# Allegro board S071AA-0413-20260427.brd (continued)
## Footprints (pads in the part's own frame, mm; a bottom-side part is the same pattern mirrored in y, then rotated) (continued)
LOGO_FY_FARADAY
  rect 4.678x4.678 smd rot 135: (-48.296,3.668) (-44.629,7.334) (-44.629,0.001) (-40.962,11.001) (-40.962,-3.666) (-37.296,0.001) (-37.296,-7.333)
  round 0.051 smd: 1(0.831,1.487)
LOGO_KT_KSMT
  round 0.051 smd: 1(-0.711,-0.711)
M3_NPTH169
  round 0.508 hole 4.293 unplated: (0,0)
OSC_3P2X2P5_4P_AKER
  rect 1.397x1.016 smd: 1(-1.1,-0.8) 2(1.1,-0.8) 3(1.1,0.8) 4(-1.1,0.8)
PCB_CODE
  round 0.051 smd: 1(0,0)
PG_VG93K_F_G1D101
  round 1.778 hole 0.711: 01(-20.32,-1.27) 02(-17.78,1.27) 03(-15.24,-1.27) 04(-12.7,1.27) 05(-10.16,-1.27) 06(-7.62,1.27) 07(-5.08,-1.27) 08(-2.54,1.27) 09(0,-1.27) 10(2.54,1.27) 11(5.08,-1.27) 12(7.62,1.27) 13(10.16,-1.27) 14(12.7,1.27) 15(15.24,-1.27) 16(17.78,1.27) 17(20.32,-1.27)
  rect 1.778x1.778 hole 0.711: A1(-20.32,-3.81) A2(-17.78,-1.27) A3(-15.24,-3.81) A4(-12.7,-1.27) A5(-10.16,-3.81) A6(-7.62,-1.27) A7(-5.08,-3.81) A8(-2.54,-1.27) A9(0,-3.81) A10(2.54,-1.27) A11(5.08,-3.81) A12(7.62,-1.27) A13(10.16,-3.81) A14(12.7,-1.27) A15(15.24,-3.81) A16(17.78,-1.27) A17(20.32,-3.81) B1(-20.32,1.27) B2(-17.78,3.81) B3(-15.24,1.27) B4(-12.7,3.81) B5(-10.16,1.27) B6(-7.62,3.81) B7(-5.08,1.27) B8(-2.54,3.81) B9(0,1.27) B10(2.54,3.81) B11(5.08,1.27) B12(7.62,3.81) B13(10.16,1.27) B14(12.7,3.81) B15(15.24,1.27) B16(17.78,3.81) B17(20.32,1.27)
PG_VG93K_F_G1D102
  round 1.778 hole 0.711: 01(-20.32,-1.27) 02(-17.78,1.27) 03(-15.24,-1.27) 04(-12.7,1.27) 05(-10.16,-1.27) 06(-7.62,1.27) 07(-5.08,-1.27) 08(-2.54,1.27) 09(0,-1.27) 10(2.54,1.27) 11(5.08,-1.27) 12(7.62,1.27) 13(10.16,-1.27) 14(12.7,1.27) 15(15.24,-1.27) 16(17.78,1.27) 17(20.32,-1.27)
  rect 1.778x1.778 hole 0.711: A1(-20.32,-3.81) A2(-17.78,-1.27) A3(-15.24,-3.81) A4(-12.7,-1.27) A5(-10.16,-3.81) A6(-7.62,-1.27) A7(-5.08,-3.81) A8(-2.54,-1.27) A9(0,-3.81) A10(2.54,-1.27) A11(5.08,-3.81) A12(7.62,-1.27) A13(10.16,-3.81) A14(12.7,-1.27) A15(15.24,-3.81) A16(17.78,-1.27) A17(20.32,-3.81) B1(-20.32,1.27) B2(-17.78,3.81) B3(-15.24,1.27) B4(-12.7,3.81) B5(-10.16,1.27) B6(-7.62,3.81) B7(-5.08,1.27) B8(-2.54,3.81) B9(0,1.27) B10(2.54,3.81) B11(5.08,1.27) B12(7.62,3.81) B13(10.16,1.27) B14(12.7,3.81) B15(15.24,1.27) B16(17.78,3.81) B17(20.32,1.27)
PG_VG93K_F_G1D103
  round 1.778 hole 0.711: 01(-20.32,-1.27) 02(-17.78,1.27) 03(-15.24,-1.27) 04(-12.7,1.27) 05(-10.16,-1.27) 06(-7.62,1.27) 07(-5.08,-1.27) 08(-2.54,1.27) 09(0,-1.27) 10(2.54,1.27) 11(5.08,-1.27) 12(7.62,1.27) 13(10.16,-1.27) 14(12.7,1.27) 15(15.24,-1.27) 16(17.78,1.27) 17(20.32,-1.27)
  rect 1.778x1.778 hole 0.711: A1(-20.32,-3.81) A2(-17.78,-1.27) A3(-15.24,-3.81) A4(-12.7,-1.27) A5(-10.16,-3.81) A6(-7.62,-1.27) A7(-5.08,-3.81) A8(-2.54,-1.27) A9(0,-3.81) A10(2.54,-1.27) A11(5.08,-3.81) A12(7.62,-1.27) A13(10.16,-3.81) A14(12.7,-1.27) A15(15.24,-3.81) A16(17.78,-1.27) A17(20.32,-3.81) B1(-20.32,1.27) B2(-17.78,3.81) B3(-15.24,1.27) B4(-12.7,3.81) B5(-10.16,1.27) B6(-7.62,3.81) B7(-5.08,1.27) B8(-2.54,3.81) B9(0,1.27) B10(2.54,3.81) B11(5.08,1.27) B12(7.62,3.81) B13(10.16,1.27) B14(12.7,3.81) B15(15.24,1.27) B16(17.78,3.81) B17(20.32,1.27)
PG_VG93K_F_G1D104
  round 1.778 hole 0.711: 01(-20.32,-1.27) 02(-17.78,1.27) 03(-15.24,-1.27) 04(-12.7,1.27) 05(-10.16,-1.27) 06(-7.62,1.27) 07(-5.08,-1.27) 08(-2.54,1.27) 09(0,-1.27) 10(2.54,1.27) 11(5.08,-1.27) 12(7.62,1.27) 13(10.16,-1.27) 14(12.7,1.27) 15(15.24,-1.27) 16(17.78,1.27) 17(20.32,-1.27)
  rect 1.778x1.778 hole 0.711: A1(-20.32,-3.81) A2(-17.78,-1.27) A3(-15.24,-3.81) A4(-12.7,-1.27) A5(-10.16,-3.81) A6(-7.62,-1.27) A7(-5.08,-3.81) A8(-2.54,-1.27) A9(0,-3.81) A10(2.54,-1.27) A11(5.08,-3.81) A12(7.62,-1.27) A13(10.16,-3.81) A14(12.7,-1.27) A15(15.24,-3.81) A16(17.78,-1.27) A17(20.32,-3.81) B1(-20.32,1.27) B2(-17.78,3.81) B3(-15.24,1.27) B4(-12.7,3.81) B5(-10.16,1.27) B6(-7.62,3.81) B7(-5.08,1.27) B8(-2.54,3.81) B9(0,1.27) B10(2.54,3.81) B11(5.08,1.27) B12(7.62,3.81) B13(10.16,1.27) B14(12.7,3.81) B15(15.24,1.27) B16(17.78,3.81) B17(20.32,1.27)
PG_VG93K_F_G1D105
  round 1.778 hole 0.711: 01(-20.32,-1.27) 02(-17.78,1.27) 03(-15.24,-1.27) 04(-12.7,1.27) 05(-10.16,-1.27) 06(-7.62,1.27) 07(-5.08,-1.27) 08(-2.54,1.27) 09(0,-1.27) 10(2.54,1.27) 11(5.08,-1.27) 12(7.62,1.27) 13(10.16,-1.27) 14(12.7,1.27) 15(15.24,-1.27) 16(17.78,1.27) 17(20.32,-1.27)
  rect 1.778x1.778 hole 0.711: A1(-20.32,-3.81) A2(-17.78,-1.27) A3(-15.24,-3.81) A4(-12.7,-1.27) A5(-10.16,-3.81) A6(-7.62,-1.27) A7(-5.08,-3.81) A8(-2.54,-1.27) A9(0,-3.81) A10(2.54,-1.27) A11(5.08,-3.81) A12(7.62,-1.27) A13(10.16,-3.81) A14(12.7,-1.27) A15(15.24,-3.81) A16(17.78,-1.27) A17(20.32,-3.81) B1(-20.32,1.27) B2(-17.78,3.81) B3(-15.24,1.27) B4(-12.7,3.81) B5(-10.16,1.27) B6(-7.62,3.81) B7(-5.08,1.27) B8(-2.54,3.81) B9(0,1.27) B10(2.54,3.81) B11(5.08,1.27) B12(7.62,3.81) B13(10.16,1.27) B14(12.7,3.81) B15(15.24,1.27) B16(17.78,3.81) B17(20.32,1.27)
PG_VG93K_F_G1D106
  round 1.778 hole 0.711: 01(-20.32,-1.27) 02(-17.78,1.27) 03(-15.24,-1.27) 04(-12.7,1.27) 05(-10.16,-1.27) 06(-7.62,1.27) 07(-5.08,-1.27) 08(-2.54,1.27) 09(0,-1.27) 10(2.54,1.27) 11(5.08,-1.27) 12(7.62,1.27) 13(10.16,-1.27) 14(12.7,1.27) 15(15.24,-1.27) 16(17.78,1.27) 17(20.32,-1.27)
  rect 1.778x1.778 hole 0.711: A1(-20.32,-3.81) A2(-17.78,-1.27) A3(-15.24,-3.81) A4(-12.7,-1.27) A5(-10.16,-3.81) A6(-7.62,-1.27) A7(-5.08,-3.81) A8(-2.54,-1.27) A9(0,-3.81) A10(2.54,-1.27) A11(5.08,-3.81) A12(7.62,-1.27) A13(10.16,-3.81) A14(12.7,-1.27) A15(15.24,-3.81) A16(17.78,-1.27) A17(20.32,-3.81) B1(-20.32,1.27) B2(-17.78,3.81) B3(-15.24,1.27) B4(-12.7,3.81) B5(-10.16,1.27) B6(-7.62,3.81) B7(-5.08,1.27) B8(-2.54,3.81) B9(0,1.27) B10(2.54,3.81) B11(5.08,1.27) B12(7.62,3.81) B13(10.16,1.27) B14(12.7,3.81) B15(15.24,1.27) B16(17.78,3.81) B17(20.32,1.27)
PG_VG93K_F_G1D107
  round 1.778 hole 0.711: 01(-20.32,-1.27) 02(-17.78,1.27) 03(-15.24,-1.27) 04(-12.7,1.27) 05(-10.16,-1.27) 06(-7.62,1.27) 07(-5.08,-1.27) 08(-2.54,1.27) 09(0,-1.27) 10(2.54,1.27) 11(5.08,-1.27) 12(7.62,1.27) 13(10.16,-1.27) 14(12.7,1.27) 15(15.24,-1.27) 16(17.78,1.27) 17(20.32,-1.27)
  rect 1.778x1.778 hole 0.711: A1(-20.32,-3.81) A2(-17.78,-1.27) A3(-15.24,-3.81) A4(-12.7,-1.27) A5(-10.16,-3.81) A6(-7.62,-1.27) A7(-5.08,-3.81) A8(-2.54,-1.27) A9(0,-3.81) A10(2.54,-1.27) A11(5.08,-3.81) A12(7.62,-1.27) A13(10.16,-3.81) A14(12.7,-1.27) A15(15.24,-3.81) A16(17.78,-1.27) A17(20.32,-3.81) B1(-20.32,1.27) B2(-17.78,3.81) B3(-15.24,1.27) B4(-12.7,3.81) B5(-10.16,1.27) B6(-7.62,3.81) B7(-5.08,1.27) B8(-2.54,3.81) B9(0,1.27) B10(2.54,3.81) B11(5.08,1.27) B12(7.62,3.81) B13(10.16,1.27) B14(12.7,3.81) B15(15.24,1.27) B16(17.78,3.81) B17(20.32,1.27)
PG_VG93K_F_G1D108
  round 1.778 hole 0.711: 01(-20.32,-1.27) 02(-17.78,1.27) 03(-15.24,-1.27) 04(-12.7,1.27) 05(-10.16,-1.27) 06(-7.62,1.27) 07(-5.08,-1.27) 08(-2.54,1.27) 09(0,-1.27) 10(2.54,1.27) 11(5.08,-1.27) 12(7.62,1.27) 13(10.16,-1.27) 14(12.7,1.27) 15(15.24,-1.27) 16(17.78,1.27) 17(20.32,-1.27)
  rect 1.778x1.778 hole 0.711: A1(-20.32,-3.81) A2(-17.78,-1.27) A3(-15.24,-3.81) A4(-12.7,-1.27) A5(-10.16,-3.81) A6(-7.62,-1.27) A7(-5.08,-3.81) A8(-2.54,-1.27) A9(0,-3.81) A10(2.54,-1.27) A11(5.08,-3.81) A12(7.62,-1.27) A13(10.16,-3.81) A14(12.7,-1.27) A15(15.24,-3.81) A16(17.78,-1.27) A17(20.32,-3.81) B1(-20.32,1.27) B2(-17.78,3.81) B3(-15.24,1.27) B4(-12.7,3.81) B5(-10.16,1.27) B6(-7.62,3.81) B7(-5.08,1.27) B8(-2.54,3.81) B9(0,1.27) B10(2.54,3.81) B11(5.08,1.27) B12(7.62,3.81) B13(10.16,1.27) B14(12.7,3.81) B15(15.24,1.27) B16(17.78,3.81) B17(20.32,1.27)
PG_VG93K_F_G1DPS1
  round 1.778 hole 0.711: A01(-20.32,-2.54) A02(-17.78,-2.54) A03(-15.24,-2.54) A04(-12.7,-2.54) A05(-10.16,-2.54) A06(-7.62,-2.54) A07(-5.08,-2.54) A08(-2.54,-2.54) A09(0,-2.54) A10(2.54,-2.54) A11(5.08,-2.54) A12(7.62,-2.54) A13(10.16,-2.54) A14(12.7,-2.54) A15(15.24,-2.54) A16(17.78,-2.54) A17(20.32,-2.54) B01(-20.32,0) B02(-17.78,0) B03(-15.24,0) B04(-12.7,0) B05(-10.16,0) B06(-7.62,0) B07(-5.08,0) B08(-2.54,0) B09(0,0) B10(2.54,0) B11(5.08,0) B12(7.62,0) B13(10.16,0) B14(12.7,0) B15(15.24,0) B16(17.78,0) B17(20.32,0) C01(-20.32,2.54) C02(-17.78,2.54) C03(-15.24,2.54) C04(-12.7,2.54) C05(-10.16,2.54) C06(-7.62,2.54) C07(-5.08,2.54) C08(-2.54,2.54) C09(0,2.54) C10(2.54,2.54) C11(5.08,2.54) C12(7.62,2.54) C13(10.16,2.54) C14(12.7,2.54) C15(15.24,2.54) C16(17.78,2.54) C17(20.32,2.54)
PG_VG93K_F_G1UTI2
  round 1.778 hole 0.711: A01(-20.32,-1.27) A02(-17.78,-1.27) A03(-15.24,-1.27) A04(-12.7,-1.27) A05(-10.16,-1.27) A06(-7.62,-1.27) A07(-5.08,-1.27) A08(-2.54,-1.27) A09(0,-1.27) A10(2.54,-1.27) A11(5.08,-1.27) A12(7.62,-1.27) A13(10.16,-1.27) A14(12.7,-1.27) A15(15.24,-1.27) A16(17.78,-1.27) A17(20.32,-1.27) B01(-20.32,1.27) B02(-17.78,1.27) B03(-15.24,1.27) B04(-12.7,1.27) B05(-10.16,1.27) B06(-7.62,1.27) B07(-5.08,1.27) B08(-2.54,1.27) B09(0,1.27) B10(2.54,1.27) B11(5.08,1.27) B12(7.62,1.27) B13(10.16,1.27) B14(12.7,1.27) B15(15.24,1.27) B16(17.78,1.27) B17(20.32,1.27)
PG_VG93K_F_G2D109
  round 1.778 hole 0.711: 01(20.32,1.27) 02(17.78,-1.27) 03(15.24,1.27) 04(12.7,-1.27) 05(10.16,1.27) 06(7.62,-1.27) 07(5.08,1.27) 08(2.54,-1.27) 09(0,1.27) 10(-2.54,-1.27) 11(-5.08,1.27) 12(-7.62,-1.27) 13(-10.16,1.27) 14(-12.7,-1.27) 15(-15.24,1.27) 16(-17.78,-1.27) 17(-20.32,1.27)
  rect 1.778x1.778 hole 0.711: A1(20.32,3.81) A2(17.78,1.27) A3(15.24,3.81) A4(12.7,1.27) A5(10.16,3.81) A6(7.62,1.27) A7(5.08,3.81) A8(2.54,1.27) A9(0,3.81) A10(-2.54,1.27) A11(-5.08,3.81) A12(-7.62,1.27) A13(-10.16,3.81) A14(-12.7,1.27) A15(-15.24,3.81) A16(-17.78,1.27) A17(-20.32,3.81) B1(20.32,-1.27) B2(17.78,-3.81) B3(15.24,-1.27) B4(12.7,-3.81) B5(10.16,-1.27) B6(7.62,-3.81) B7(5.08,-1.27) B8(2.54,-3.81) B9(0,-1.27) B10(-2.54,-3.81) B11(-5.08,-1.27) B12(-7.62,-3.81) B13(-10.16,-1.27) B14(-12.7,-3.81) B15(-15.24,-1.27) B16(-17.78,-3.81) B17(-20.32,-1.27)
PG_VG93K_F_G2D110
  round 1.778 hole 0.711: 01(20.32,1.27) 02(17.78,-1.27) 03(15.24,1.27) 04(12.7,-1.27) 05(10.16,1.27) 06(7.62,-1.27) 07(5.08,1.27) 08(2.54,-1.27) 09(0,1.27) 10(-2.54,-1.27) 11(-5.08,1.27) 12(-7.62,-1.27) 13(-10.16,1.27) 14(-12.7,-1.27) 15(-15.24,1.27) 16(-17.78,-1.27) 17(-20.32,1.27)
  rect 1.778x1.778 hole 0.711: A1(20.32,3.81) A2(17.78,1.27) A3(15.24,3.81) A4(12.7,1.27) A5(10.16,3.81) A6(7.62,1.27) A7(5.08,3.81) A8(2.54,1.27) A9(0,3.81) A10(-2.54,1.27) A11(-5.08,3.81) A12(-7.62,1.27) A13(-10.16,3.81) A14(-12.7,1.27) A15(-15.24,3.81) A16(-17.78,1.27) A17(-20.32,3.81) B1(20.32,-1.27) B2(17.78,-3.81) B3(15.24,-1.27) B4(12.7,-3.81) B5(10.16,-1.27) B6(7.62,-3.81) B7(5.08,-1.27) B8(2.54,-3.81) B9(0,-1.27) B10(-2.54,-3.81) B11(-5.08,-1.27) B12(-7.62,-3.81) B13(-10.16,-1.27) B14(-12.7,-3.81) B15(-15.24,-1.27) B16(-17.78,-3.81) B17(-20.32,-1.27)
PG_VG93K_F_G2D111
  round 1.778 hole 0.711: 01(20.32,1.27) 02(17.78,-1.27) 03(15.24,1.27) 04(12.7,-1.27) 05(10.16,1.27) 06(7.62,-1.27) 07(5.08,1.27) 08(2.54,-1.27) 09(0,1.27) 10(-2.54,-1.27) 11(-5.08,1.27) 12(-7.62,-1.27) 13(-10.16,1.27) 14(-12.7,-1.27) 15(-15.24,1.27) 16(-17.78,-1.27) 17(-20.32,1.27)
  rect 1.778x1.778 hole 0.711: A1(20.32,3.81) A2(17.78,1.27) A3(15.24,3.81) A4(12.7,1.27) A5(10.16,3.81) A6(7.62,1.27) A7(5.08,3.81) A8(2.54,1.27) A9(0,3.81) A10(-2.54,1.27) A11(-5.08,3.81) A12(-7.62,1.27) A13(-10.16,3.81) A14(-12.7,1.27) A15(-15.24,3.81) A16(-17.78,1.27) A17(-20.32,3.81) B1(20.32,-1.27) B2(17.78,-3.81) B3(15.24,-1.27) B4(12.7,-3.81) B5(10.16,-1.27) B6(7.62,-3.81) B7(5.08,-1.27) B8(2.54,-3.81) B9(0,-1.27) B10(-2.54,-3.81) B11(-5.08,-1.27) B12(-7.62,-3.81) B13(-10.16,-1.27) B14(-12.7,-3.81) B15(-15.24,-1.27) B16(-17.78,-3.81) B17(-20.32,-1.27)
PG_VG93K_F_G2D112
  round 1.778 hole 0.711: 01(20.32,1.27) 02(17.78,-1.27) 03(15.24,1.27) 04(12.7,-1.27) 05(10.16,1.27) 06(7.62,-1.27) 07(5.08,1.27) 08(2.54,-1.27) 09(0,1.27) 10(-2.54,-1.27) 11(-5.08,1.27) 12(-7.62,-1.27) 13(-10.16,1.27) 14(-12.7,-1.27) 15(-15.24,1.27) 16(-17.78,-1.27) 17(-20.32,1.27)
  rect 1.778x1.778 hole 0.711: A1(20.32,3.81) A2(17.78,1.27) A3(15.24,3.81) A4(12.7,1.27) A5(10.16,3.81) A6(7.62,1.27) A7(5.08,3.81) A8(2.54,1.27) A9(0,3.81) A10(-2.54,1.27) A11(-5.08,3.81) A12(-7.62,1.27) A13(-10.16,3.81) A14(-12.7,1.27) A15(-15.24,3.81) A16(-17.78,1.27) A17(-20.32,3.81) B1(20.32,-1.27) B2(17.78,-3.81) B3(15.24,-1.27) B4(12.7,-3.81) B5(10.16,-1.27) B6(7.62,-3.81) B7(5.08,-1.27) B8(2.54,-3.81) B9(0,-1.27) B10(-2.54,-3.81) B11(-5.08,-1.27) B12(-7.62,-3.81) B13(-10.16,-1.27) B14(-12.7,-3.81) B15(-15.24,-1.27) B16(-17.78,-3.81) B17(-20.32,-1.27)
PG_VG93K_F_G2D113
  round 1.778 hole 0.711: 01(20.32,1.27) 02(17.78,-1.27) 03(15.24,1.27) 04(12.7,-1.27) 05(10.16,1.27) 06(7.62,-1.27) 07(5.08,1.27) 08(2.54,-1.27) 09(0,1.27) 10(-2.54,-1.27) 11(-5.08,1.27) 12(-7.62,-1.27) 13(-10.16,1.27) 14(-12.7,-1.27) 15(-15.24,1.27) 16(-17.78,-1.27) 17(-20.32,1.27)
  rect 1.778x1.778 hole 0.711: A1(20.32,3.81) A2(17.78,1.27) A3(15.24,3.81) A4(12.7,1.27) A5(10.16,3.81) A6(7.62,1.27) A7(5.08,3.81) A8(2.54,1.27) A9(0,3.81) A10(-2.54,1.27) A11(-5.08,3.81) A12(-7.62,1.27) A13(-10.16,3.81) A14(-12.7,1.27) A15(-15.24,3.81) A16(-17.78,1.27) A17(-20.32,3.81) B1(20.32,-1.27) B2(17.78,-3.81) B3(15.24,-1.27) B4(12.7,-3.81) B5(10.16,-1.27) B6(7.62,-3.81) B7(5.08,-1.27) B8(2.54,-3.81) B9(0,-1.27) B10(-2.54,-3.81) B11(-5.08,-1.27) B12(-7.62,-3.81) B13(-10.16,-1.27) B14(-12.7,-3.81) B15(-15.24,-1.27) B16(-17.78,-3.81) B17(-20.32,-1.27)
PG_VG93K_F_G2D114
  round 1.778 hole 0.711: 01(20.32,1.27) 02(17.78,-1.27) 03(15.24,1.27) 04(12.7,-1.27) 05(10.16,1.27) 06(7.62,-1.27) 07(5.08,1.27) 08(2.54,-1.27) 09(0,1.27) 10(-2.54,-1.27) 11(-5.08,1.27) 12(-7.62,-1.27) 13(-10.16,1.27) 14(-12.7,-1.27) 15(-15.24,1.27) 16(-17.78,-1.27) 17(-20.32,1.27)
  rect 1.778x1.778 hole 0.711: A1(20.32,3.81) A2(17.78,1.27) A3(15.24,3.81) A4(12.7,1.27) A5(10.16,3.81) A6(7.62,1.27) A7(5.08,3.81) A8(2.54,1.27) A9(0,3.81) A10(-2.54,1.27) A11(-5.08,3.81) A12(-7.62,1.27) A13(-10.16,3.81) A14(-12.7,1.27) A15(-15.24,3.81) A16(-17.78,1.27) A17(-20.32,3.81) B1(20.32,-1.27) B2(17.78,-3.81) B3(15.24,-1.27) B4(12.7,-3.81) B5(10.16,-1.27) B6(7.62,-3.81) B7(5.08,-1.27) B8(2.54,-3.81) B9(0,-1.27) B10(-2.54,-3.81) B11(-5.08,-1.27) B12(-7.62,-3.81) B13(-10.16,-1.27) B14(-12.7,-3.81) B15(-15.24,-1.27) B16(-17.78,-3.81) B17(-20.32,-1.27)
PG_VG93K_F_G2D115
  round 1.778 hole 0.711: 01(20.32,1.27) 02(17.78,-1.27) 03(15.24,1.27) 04(12.7,-1.27) 05(10.16,1.27) 06(7.62,-1.27) 07(5.08,1.27) 08(2.54,-1.27) 09(0,1.27) 10(-2.54,-1.27) 11(-5.08,1.27) 12(-7.62,-1.27) 13(-10.16,1.27) 14(-12.7,-1.27) 15(-15.24,1.27) 16(-17.78,-1.27) 17(-20.32,1.27)
  rect 1.778x1.778 hole 0.711: A1(20.32,3.81) A2(17.78,1.27) A3(15.24,3.81) A4(12.7,1.27) A5(10.16,3.81) A6(7.62,1.27) A7(5.08,3.81) A8(2.54,1.27) A9(0,3.81) A10(-2.54,1.27) A11(-5.08,3.81) A12(-7.62,1.27) A13(-10.16,3.81) A14(-12.7,1.27) A15(-15.24,3.81) A16(-17.78,1.27) A17(-20.32,3.81) B1(20.32,-1.27) B2(17.78,-3.81) B3(15.24,-1.27) B4(12.7,-3.81) B5(10.16,-1.27) B6(7.62,-3.81) B7(5.08,-1.27) B8(2.54,-3.81) B9(0,-1.27) B10(-2.54,-3.81) B11(-5.08,-1.27) B12(-7.62,-3.81) B13(-10.16,-1.27) B14(-12.7,-3.81) B15(-15.24,-1.27) B16(-17.78,-3.81) B17(-20.32,-1.27)
PG_VG93K_F_G2D116
  round 1.778 hole 0.711: 01(20.32,1.27) 02(17.78,-1.27) 03(15.24,1.27) 04(12.7,-1.27) 05(10.16,1.27) 06(7.62,-1.27) 07(5.08,1.27) 08(2.54,-1.27) 09(0,1.27) 10(-2.54,-1.27) 11(-5.08,1.27) 12(-7.62,-1.27) 13(-10.16,1.27) 14(-12.7,-1.27) 15(-15.24,1.27) 16(-17.78,-1.27) 17(-20.32,1.27)
  rect 1.778x1.778 hole 0.711: A1(20.32,3.81) A2(17.78,1.27) A3(15.24,3.81) A4(12.7,1.27) A5(10.16,3.81) A6(7.62,1.27) A7(5.08,3.81) A8(2.54,1.27) A9(0,3.81) A10(-2.54,1.27) A11(-5.08,3.81) A12(-7.62,1.27) A13(-10.16,3.81) A14(-12.7,1.27) A15(-15.24,3.81) A16(-17.78,1.27) A17(-20.32,3.81) B1(20.32,-1.27) B2(17.78,-3.81) B3(15.24,-1.27) B4(12.7,-3.81) B5(10.16,-1.27) B6(7.62,-3.81) B7(5.08,-1.27) B8(2.54,-3.81) B9(0,-1.27) B10(-2.54,-3.81) B11(-5.08,-1.27) B12(-7.62,-3.81) B13(-10.16,-1.27) B14(-12.7,-3.81) B15(-15.24,-1.27) B16(-17.78,-3.81) B17(-20.32,-1.27)
PG_VG93K_F_G2DPS2
  round 1.778 hole 0.711: A01(20.32,2.54) A02(17.78,2.54) A03(15.24,2.54) A04(12.7,2.54) A05(10.16,2.54) A06(7.62,2.54) A07(5.08,2.54) A08(2.54,2.54) A09(0,2.54) A10(-2.54,2.54) A11(-5.08,2.54) A12(-7.62,2.54) A13(-10.16,2.54) A14(-12.7,2.54) A15(-15.24,2.54) A16(-17.78,2.54) A17(-20.32,2.54) B01(20.32,0) B02(17.78,0) B03(15.24,0) B04(12.7,0) B05(10.16,0) B06(7.62,0) B07(5.08,0) B08(2.54,0) B09(0,0) B10(-2.54,0) B11(-5.08,0) B12(-7.62,0) B13(-10.16,0) B14(-12.7,0) B15(-15.24,0) B16(-17.78,0) B17(-20.32,0) C01(20.32,-2.54) C02(17.78,-2.54) C03(15.24,-2.54) C04(12.7,-2.54) C05(10.16,-2.54) C06(7.62,-2.54) C07(5.08,-2.54) C08(2.54,-2.54) C09(0,-2.54) C10(-2.54,-2.54) C11(-5.08,-2.54) C12(-7.62,-2.54) C13(-10.16,-2.54) C14(-12.7,-2.54) C15(-15.24,-2.54) C16(-17.78,-2.54) C17(-20.32,-2.54)
PG_VG93K_F_G2UTI3
  round 1.778 hole 0.711: A01(20.32,1.27) A02(17.78,1.27) A03(15.24,1.27) A04(12.7,1.27) A05(10.16,1.27) A06(7.62,1.27) A07(5.08,1.27) A08(2.54,1.27) A09(0,1.27) A10(-2.54,1.27) A11(-5.08,1.27) A12(-7.62,1.27) A13(-10.16,1.27) A14(-12.7,1.27) A15(-15.24,1.27) A16(-17.78,1.27) A17(-20.32,1.27) B01(20.32,-1.27) B02(17.78,-1.27) B03(15.24,-1.27) B04(12.7,-1.27) B05(10.16,-1.27) B06(7.62,-1.27) B07(5.08,-1.27) B08(2.54,-1.27) B09(0,-1.27) B10(-2.54,-1.27) B11(-5.08,-1.27) B12(-7.62,-1.27) B13(-10.16,-1.27) B14(-12.7,-1.27) B15(-15.24,-1.27) B16(-17.78,-1.27) B17(-20.32,-1.27)
PG_VG93K_F_G3D117
  round 1.778 hole 0.711: 01(-20.32,-1.27) 02(-17.78,1.27) 03(-15.24,-1.27) 04(-12.7,1.27) 05(-10.16,-1.27) 06(-7.62,1.27) 07(-5.08,-1.27) 08(-2.54,1.27) 09(0,-1.27) 10(2.54,1.27) 11(5.08,-1.27) 12(7.62,1.27) 13(10.16,-1.27) 14(12.7,1.27) 15(15.24,-1.27) 16(17.78,1.27) 17(20.32,-1.27)
  rect 1.778x1.778 hole 0.711: A1(-20.32,-3.81) A2(-17.78,-1.27) A3(-15.24,-3.81) A4(-12.7,-1.27) A5(-10.16,-3.81) A6(-7.62,-1.27) A7(-5.08,-3.81) A8(-2.54,-1.27) A9(0,-3.81) A10(2.54,-1.27) A11(5.08,-3.81) A12(7.62,-1.27) A13(10.16,-3.81) A14(12.7,-1.27) A15(15.24,-3.81) A16(17.78,-1.27) A17(20.32,-3.81) B1(-20.32,1.27) B2(-17.78,3.81) B3(-15.24,1.27) B4(-12.7,3.81) B5(-10.16,1.27) B6(-7.62,3.81) B7(-5.08,1.27) B8(-2.54,3.81) B9(0,1.27) B10(2.54,3.81) B11(5.08,1.27) B12(7.62,3.81) B13(10.16,1.27) B14(12.7,3.81) B15(15.24,1.27) B16(17.78,3.81) B17(20.32,1.27)
PG_VG93K_F_G3D118
  round 1.778 hole 0.711: 01(-20.32,-1.27) 02(-17.78,1.27) 03(-15.24,-1.27) 04(-12.7,1.27) 05(-10.16,-1.27) 06(-7.62,1.27) 07(-5.08,-1.27) 08(-2.54,1.27) 09(0,-1.27) 10(2.54,1.27) 11(5.08,-1.27) 12(7.62,1.27) 13(10.16,-1.27) 14(12.7,1.27) 15(15.24,-1.27) 16(17.78,1.27) 17(20.32,-1.27)
  rect 1.778x1.778 hole 0.711: A1(-20.32,-3.81) A2(-17.78,-1.27) A3(-15.24,-3.81) A4(-12.7,-1.27) A5(-10.16,-3.81) A6(-7.62,-1.27) A7(-5.08,-3.81) A8(-2.54,-1.27) A9(0,-3.81) A10(2.54,-1.27) A11(5.08,-3.81) A12(7.62,-1.27) A13(10.16,-3.81) A14(12.7,-1.27) A15(15.24,-3.81) A16(17.78,-1.27) A17(20.32,-3.81) B1(-20.32,1.27) B2(-17.78,3.81) B3(-15.24,1.27) B4(-12.7,3.81) B5(-10.16,1.27) B6(-7.62,3.81) B7(-5.08,1.27) B8(-2.54,3.81) B9(0,1.27) B10(2.54,3.81) B11(5.08,1.27) B12(7.62,3.81) B13(10.16,1.27) B14(12.7,3.81) B15(15.24,1.27) B16(17.78,3.81) B17(20.32,1.27)
PG_VG93K_F_G3D119
  round 1.778 hole 0.711: 01(-20.32,-1.27) 02(-17.78,1.27) 03(-15.24,-1.27) 04(-12.7,1.27) 05(-10.16,-1.27) 06(-7.62,1.27) 07(-5.08,-1.27) 08(-2.54,1.27) 09(0,-1.27) 10(2.54,1.27) 11(5.08,-1.27) 12(7.62,1.27) 13(10.16,-1.27) 14(12.7,1.27) 15(15.24,-1.27) 16(17.78,1.27) 17(20.32,-1.27)
  rect 1.778x1.778 hole 0.711: A1(-20.32,-3.81) A2(-17.78,-1.27) A3(-15.24,-3.81) A4(-12.7,-1.27) A5(-10.16,-3.81) A6(-7.62,-1.27) A7(-5.08,-3.81) A8(-2.54,-1.27) A9(0,-3.81) A10(2.54,-1.27) A11(5.08,-3.81) A12(7.62,-1.27) A13(10.16,-3.81) A14(12.7,-1.27) A15(15.24,-3.81) A16(17.78,-1.27) A17(20.32,-3.81) B1(-20.32,1.27) B2(-17.78,3.81) B3(-15.24,1.27) B4(-12.7,3.81) B5(-10.16,1.27) B6(-7.62,3.81) B7(-5.08,1.27) B8(-2.54,3.81) B9(0,1.27) B10(2.54,3.81) B11(5.08,1.27) B12(7.62,3.81) B13(10.16,1.27) B14(12.7,3.81) B15(15.24,1.27) B16(17.78,3.81) B17(20.32,1.27)
PG_VG93K_F_G3D120
  round 1.778 hole 0.711: 01(-20.32,-1.27) 02(-17.78,1.27) 03(-15.24,-1.27) 04(-12.7,1.27) 05(-10.16,-1.27) 06(-7.62,1.27) 07(-5.08,-1.27) 08(-2.54,1.27) 09(0,-1.27) 10(2.54,1.27) 11(5.08,-1.27) 12(7.62,1.27) 13(10.16,-1.27) 14(12.7,1.27) 15(15.24,-1.27) 16(17.78,1.27) 17(20.32,-1.27)
  rect 1.778x1.778 hole 0.711: A1(-20.32,-3.81) A2(-17.78,-1.27) A3(-15.24,-3.81) A4(-12.7,-1.27) A5(-10.16,-3.81) A6(-7.62,-1.27) A7(-5.08,-3.81) A8(-2.54,-1.27) A9(0,-3.81) A10(2.54,-1.27) A11(5.08,-3.81) A12(7.62,-1.27) A13(10.16,-3.81) A14(12.7,-1.27) A15(15.24,-3.81) A16(17.78,-1.27) A17(20.32,-3.81) B1(-20.32,1.27) B2(-17.78,3.81) B3(-15.24,1.27) B4(-12.7,3.81) B5(-10.16,1.27) B6(-7.62,3.81) B7(-5.08,1.27) B8(-2.54,3.81) B9(0,1.27) B10(2.54,3.81) B11(5.08,1.27) B12(7.62,3.81) B13(10.16,1.27) B14(12.7,3.81) B15(15.24,1.27) B16(17.78,3.81) B17(20.32,1.27)
PG_VG93K_F_G3D121
  round 1.778 hole 0.711: 01(-20.32,-1.27) 02(-17.78,1.27) 03(-15.24,-1.27) 04(-12.7,1.27) 05(-10.16,-1.27) 06(-7.62,1.27) 07(-5.08,-1.27) 08(-2.54,1.27) 09(0,-1.27) 10(2.54,1.27) 11(5.08,-1.27) 12(7.62,1.27) 13(10.16,-1.27) 14(12.7,1.27) 15(15.24,-1.27) 16(17.78,1.27) 17(20.32,-1.27)
  rect 1.778x1.778 hole 0.711: A1(-20.32,-3.81) A2(-17.78,-1.27) A3(-15.24,-3.81) A4(-12.7,-1.27) A5(-10.16,-3.81) A6(-7.62,-1.27) A7(-5.08,-3.81) A8(-2.54,-1.27) A9(0,-3.81) A10(2.54,-1.27) A11(5.08,-3.81) A12(7.62,-1.27) A13(10.16,-3.81) A14(12.7,-1.27) A15(15.24,-3.81) A16(17.78,-1.27) A17(20.32,-3.81) B1(-20.32,1.27) B2(-17.78,3.81) B3(-15.24,1.27) B4(-12.7,3.81) B5(-10.16,1.27) B6(-7.62,3.81) B7(-5.08,1.27) B8(-2.54,3.81) B9(0,1.27) B10(2.54,3.81) B11(5.08,1.27) B12(7.62,3.81) B13(10.16,1.27) B14(12.7,3.81) B15(15.24,1.27) B16(17.78,3.81) B17(20.32,1.27)
PG_VG93K_F_G3D122
  round 1.778 hole 0.711: 01(-20.32,-1.27) 02(-17.78,1.27) 03(-15.24,-1.27) 04(-12.7,1.27) 05(-10.16,-1.27) 06(-7.62,1.27) 07(-5.08,-1.27) 08(-2.54,1.27) 09(0,-1.27) 10(2.54,1.27) 11(5.08,-1.27) 12(7.62,1.27) 13(10.16,-1.27) 14(12.7,1.27) 15(15.24,-1.27) 16(17.78,1.27) 17(20.32,-1.27)
  rect 1.778x1.778 hole 0.711: A1(-20.32,-3.81) A2(-17.78,-1.27) A3(-15.24,-3.81) A4(-12.7,-1.27) A5(-10.16,-3.81) A6(-7.62,-1.27) A7(-5.08,-3.81) A8(-2.54,-1.27) A9(0,-3.81) A10(2.54,-1.27) A11(5.08,-3.81) A12(7.62,-1.27) A13(10.16,-3.81) A14(12.7,-1.27) A15(15.24,-3.81) A16(17.78,-1.27) A17(20.32,-3.81) B1(-20.32,1.27) B2(-17.78,3.81) B3(-15.24,1.27) B4(-12.7,3.81) B5(-10.16,1.27) B6(-7.62,3.81) B7(-5.08,1.27) B8(-2.54,3.81) B9(0,1.27) B10(2.54,3.81) B11(5.08,1.27) B12(7.62,3.81) B13(10.16,1.27) B14(12.7,3.81) B15(15.24,1.27) B16(17.78,3.81) B17(20.32,1.27)
PG_VG93K_F_G3D123
  round 1.778 hole 0.711: 01(-20.32,-1.27) 02(-17.78,1.27) 03(-15.24,-1.27) 04(-12.7,1.27) 05(-10.16,-1.27) 06(-7.62,1.27) 07(-5.08,-1.27) 08(-2.54,1.27) 09(0,-1.27) 10(2.54,1.27) 11(5.08,-1.27) 12(7.62,1.27) 13(10.16,-1.27) 14(12.7,1.27) 15(15.24,-1.27) 16(17.78,1.27) 17(20.32,-1.27)
  rect 1.778x1.778 hole 0.711: A1(-20.32,-3.81) A2(-17.78,-1.27) A3(-15.24,-3.81) A4(-12.7,-1.27) A5(-10.16,-3.81) A6(-7.62,-1.27) A7(-5.08,-3.81) A8(-2.54,-1.27) A9(0,-3.81) A10(2.54,-1.27) A11(5.08,-3.81) A12(7.62,-1.27) A13(10.16,-3.81) A14(12.7,-1.27) A15(15.24,-3.81) A16(17.78,-1.27) A17(20.32,-3.81) B1(-20.32,1.27) B2(-17.78,3.81) B3(-15.24,1.27) B4(-12.7,3.81) B5(-10.16,1.27) B6(-7.62,3.81) B7(-5.08,1.27) B8(-2.54,3.81) B9(0,1.27) B10(2.54,3.81) B11(5.08,1.27) B12(7.62,3.81) B13(10.16,1.27) B14(12.7,3.81) B15(15.24,1.27) B16(17.78,3.81) B17(20.32,1.27)
PG_VG93K_F_G3D124
  round 1.778 hole 0.711: 01(-20.32,-1.27) 02(-17.78,1.27) 03(-15.24,-1.27) 04(-12.7,1.27) 05(-10.16,-1.27) 06(-7.62,1.27) 07(-5.08,-1.27) 08(-2.54,1.27) 09(0,-1.27) 10(2.54,1.27) 11(5.08,-1.27) 12(7.62,1.27) 13(10.16,-1.27) 14(12.7,1.27) 15(15.24,-1.27) 16(17.78,1.27) 17(20.32,-1.27)
  rect 1.778x1.778 hole 0.711: A1(-20.32,-3.81) A2(-17.78,-1.27) A3(-15.24,-3.81) A4(-12.7,-1.27) A5(-10.16,-3.81) A6(-7.62,-1.27) A7(-5.08,-3.81) A8(-2.54,-1.27) A9(0,-3.81) A10(2.54,-1.27) A11(5.08,-3.81) A12(7.62,-1.27) A13(10.16,-3.81) A14(12.7,-1.27) A15(15.24,-3.81) A16(17.78,-1.27) A17(20.32,-3.81) B1(-20.32,1.27) B2(-17.78,3.81) B3(-15.24,1.27) B4(-12.7,3.81) B5(-10.16,1.27) B6(-7.62,3.81) B7(-5.08,1.27) B8(-2.54,3.81) B9(0,1.27) B10(2.54,3.81) B11(5.08,1.27) B12(7.62,3.81) B13(10.16,1.27) B14(12.7,3.81) B15(15.24,1.27) B16(17.78,3.81) B17(20.32,1.27)
PG_VG93K_F_G3DPS3
  round 1.778 hole 0.711: A01(-20.32,-2.54) A02(-17.78,-2.54) A03(-15.24,-2.54) A04(-12.7,-2.54) A05(-10.16,-2.54) A06(-7.62,-2.54) A07(-5.08,-2.54) A08(-2.54,-2.54) A09(0,-2.54) A10(2.54,-2.54) A11(5.08,-2.54) A12(7.62,-2.54) A13(10.16,-2.54) A14(12.7,-2.54) A15(15.24,-2.54) A16(17.78,-2.54) A17(20.32,-2.54) B01(-20.32,0) B02(-17.78,0) B03(-15.24,0) B04(-12.7,0) B05(-10.16,0) B06(-7.62,0) B07(-5.08,0) B08(-2.54,0) B09(0,0) B10(2.54,0) B11(5.08,0) B12(7.62,0) B13(10.16,0) B14(12.7,0) B15(15.24,0) B16(17.78,0) B17(20.32,0) C01(-20.32,2.54) C02(-17.78,2.54) C03(-15.24,2.54) C04(-12.7,2.54) C05(-10.16,2.54) C06(-7.62,2.54) C07(-5.08,2.54) C08(-2.54,2.54) C09(0,2.54) C10(2.54,2.54) C11(5.08,2.54) C12(7.62,2.54) C13(10.16,2.54) C14(12.7,2.54) C15(15.24,2.54) C16(17.78,2.54) C17(20.32,2.54)
PG_VG93K_F_G3UTI1
  round 1.778 hole 0.711: A01(-20.32,-1.27) A02(-17.78,-1.27) A03(-15.24,-1.27) A04(-12.7,-1.27) A05(-10.16,-1.27) A06(-7.62,-1.27) A07(-5.08,-1.27) A08(-2.54,-1.27) A09(0,-1.27) A10(2.54,-1.27) A11(5.08,-1.27) A12(7.62,-1.27) A13(10.16,-1.27) A14(12.7,-1.27) A15(15.24,-1.27) A16(17.78,-1.27) A17(20.32,-1.27) B01(-20.32,1.27) B02(-17.78,1.27) B03(-15.24,1.27) B04(-12.7,1.27) B05(-10.16,1.27) B06(-7.62,1.27) B07(-5.08,1.27) B08(-2.54,1.27) B09(0,1.27) B10(2.54,1.27) B11(5.08,1.27) B12(7.62,1.27) B13(10.16,1.27) B14(12.7,1.27) B15(15.24,1.27) B16(17.78,1.27) B17(20.32,1.27)
PG_VG93K_F_G8D227
  round 1.778 hole 0.711: 01(20.32,1.27) 02(17.78,-1.27) 03(15.24,1.27) 04(12.7,-1.27) 05(10.16,1.27) 06(7.62,-1.27) 07(5.08,1.27) 08(2.54,-1.27) 09(0,1.27) 10(-2.54,-1.27) 11(-5.08,1.27) 12(-7.62,-1.27) 13(-10.16,1.27) 14(-12.7,-1.27) 15(-15.24,1.27) 16(-17.78,-1.27) 17(-20.32,1.27)
  rect 1.778x1.778 hole 0.711: A1(20.32,3.81) A2(17.78,1.27) A3(15.24,3.81) A4(12.7,1.27) A5(10.16,3.81) A6(7.62,1.27) A7(5.08,3.81) A8(2.54,1.27) A9(0,3.81) A10(-2.54,1.27) A11(-5.08,3.81) A12(-7.62,1.27) A13(-10.16,3.81) A14(-12.7,1.27) A15(-15.24,3.81) A16(-17.78,1.27) A17(-20.32,3.81) B1(20.32,-1.27) B2(17.78,-3.81) B3(15.24,-1.27) B4(12.7,-3.81) B5(10.16,-1.27) B6(7.62,-3.81) B7(5.08,-1.27) B8(2.54,-3.81) B9(0,-1.27) B10(-2.54,-3.81) B11(-5.08,-1.27) B12(-7.62,-3.81) B13(-10.16,-1.27) B14(-12.7,-3.81) B15(-15.24,-1.27) B16(-17.78,-3.81) B17(-20.32,-1.27)
PG_VG93K_F_G8D228
  round 1.778 hole 0.711: 01(20.32,1.27) 02(17.78,-1.27) 03(15.24,1.27) 04(12.7,-1.27) 05(10.16,1.27) 06(7.62,-1.27) 07(5.08,1.27) 08(2.54,-1.27) 09(0,1.27) 10(-2.54,-1.27) 11(-5.08,1.27) 12(-7.62,-1.27) 13(-10.16,1.27) 14(-12.7,-1.27) 15(-15.24,1.27) 16(-17.78,-1.27) 17(-20.32,1.27)
  rect 1.778x1.778 hole 0.711: A1(20.32,3.81) A2(17.78,1.27) A3(15.24,3.81) A4(12.7,1.27) A5(10.16,3.81) A6(7.62,1.27) A7(5.08,3.81) A8(2.54,1.27) A9(0,3.81) A10(-2.54,1.27) A11(-5.08,3.81) A12(-7.62,1.27) A13(-10.16,3.81) A14(-12.7,1.27) A15(-15.24,3.81) A16(-17.78,1.27) A17(-20.32,3.81) B1(20.32,-1.27) B2(17.78,-3.81) B3(15.24,-1.27) B4(12.7,-3.81) B5(10.16,-1.27) B6(7.62,-3.81) B7(5.08,-1.27) B8(2.54,-3.81) B9(0,-1.27) B10(-2.54,-3.81) B11(-5.08,-1.27) B12(-7.62,-3.81) B13(-10.16,-1.27) B14(-12.7,-3.81) B15(-15.24,-1.27) B16(-17.78,-3.81) B17(-20.32,-1.27)
PG_VG93K_F_G8D231
  round 1.778 hole 0.711: 01(20.32,1.27) 02(17.78,-1.27) 03(15.24,1.27) 04(12.7,-1.27) 05(10.16,1.27) 06(7.62,-1.27) 07(5.08,1.27) 08(2.54,-1.27) 09(0,1.27) 10(-2.54,-1.27) 11(-5.08,1.27) 12(-7.62,-1.27) 13(-10.16,1.27) 14(-12.7,-1.27) 15(-15.24,1.27) 16(-17.78,-1.27) 17(-20.32,1.27)
  rect 1.778x1.778 hole 0.711: A1(20.32,3.81) A2(17.78,1.27) A3(15.24,3.81) A4(12.7,1.27) A5(10.16,3.81) A6(7.62,1.27) A7(5.08,3.81) A8(2.54,1.27) A9(0,3.81) A10(-2.54,1.27) A11(-5.08,3.81) A12(-7.62,1.27) A13(-10.16,3.81) A14(-12.7,1.27) A15(-15.24,3.81) A16(-17.78,1.27) A17(-20.32,3.81) B1(20.32,-1.27) B2(17.78,-3.81) B3(15.24,-1.27) B4(12.7,-3.81) B5(10.16,-1.27) B6(7.62,-3.81) B7(5.08,-1.27) B8(2.54,-3.81) B9(0,-1.27) B10(-2.54,-3.81) B11(-5.08,-1.27) B12(-7.62,-3.81) B13(-10.16,-1.27) B14(-12.7,-3.81) B15(-15.24,-1.27) B16(-17.78,-3.81) B17(-20.32,-1.27)
PG_VG93K_F_G8D232
  round 1.778 hole 0.711: 01(20.32,1.27) 02(17.78,-1.27) 03(15.24,1.27) 04(12.7,-1.27) 05(10.16,1.27) 06(7.62,-1.27) 07(5.08,1.27) 08(2.54,-1.27) 09(0,1.27) 10(-2.54,-1.27) 11(-5.08,1.27) 12(-7.62,-1.27) 13(-10.16,1.27) 14(-12.7,-1.27) 15(-15.24,1.27) 16(-17.78,-1.27) 17(-20.32,1.27)
  rect 1.778x1.778 hole 0.711: A1(20.32,3.81) A2(17.78,1.27) A3(15.24,3.81) A4(12.7,1.27) A5(10.16,3.81) A6(7.62,1.27) A7(5.08,3.81) A8(2.54,1.27) A9(0,3.81) A10(-2.54,1.27) A11(-5.08,3.81) A12(-7.62,1.27) A13(-10.16,3.81) A14(-12.7,1.27) A15(-15.24,3.81) A16(-17.78,1.27) A17(-20.32,3.81) B1(20.32,-1.27) B2(17.78,-3.81) B3(15.24,-1.27) B4(12.7,-3.81) B5(10.16,-1.27) B6(7.62,-3.81) B7(5.08,-1.27) B8(2.54,-3.81) B9(0,-1.27) B10(-2.54,-3.81) B11(-5.08,-1.27) B12(-7.62,-3.81) B13(-10.16,-1.27) B14(-12.7,-3.81) B15(-15.24,-1.27) B16(-17.78,-3.81) B17(-20.32,-1.27)
PG_VG93K_F_G8D427
  round 1.778 hole 0.711: 01(20.32,1.27) 02(17.78,-1.27) 03(15.24,1.27) 04(12.7,-1.27) 05(10.16,1.27) 06(7.62,-1.27) 07(5.08,1.27) 08(2.54,-1.27) 09(0,1.27) 10(-2.54,-1.27) 11(-5.08,1.27) 12(-7.62,-1.27) 13(-10.16,1.27) 14(-12.7,-1.27) 15(-15.24,1.27) 16(-17.78,-1.27) 17(-20.32,1.27)
  rect 1.778x1.778 hole 0.711: A1(20.32,3.81) A2(17.78,1.27) A3(15.24,3.81) A4(12.7,1.27) A5(10.16,3.81) A6(7.62,1.27) A7(5.08,3.81) A8(2.54,1.27) A9(0,3.81) A10(-2.54,1.27) A11(-5.08,3.81) A12(-7.62,1.27) A13(-10.16,3.81) A14(-12.7,1.27) A15(-15.24,3.81) A16(-17.78,1.27) A17(-20.32,3.81) B1(20.32,-1.27) B2(17.78,-3.81) B3(15.24,-1.27) B4(12.7,-3.81) B5(10.16,-1.27) B6(7.62,-3.81) B7(5.08,-1.27) B8(2.54,-3.81) B9(0,-1.27) B10(-2.54,-3.81) B11(-5.08,-1.27) B12(-7.62,-3.81) B13(-10.16,-1.27) B14(-12.7,-3.81) B15(-15.24,-1.27) B16(-17.78,-3.81) B17(-20.32,-1.27)
PG_VG93K_F_G8D428
  round 1.778 hole 0.711: 01(20.32,1.27) 02(17.78,-1.27) 03(15.24,1.27) 04(12.7,-1.27) 05(10.16,1.27) 06(7.62,-1.27) 07(5.08,1.27) 08(2.54,-1.27) 09(0,1.27) 10(-2.54,-1.27) 11(-5.08,1.27) 12(-7.62,-1.27) 13(-10.16,1.27) 14(-12.7,-1.27) 15(-15.24,1.27) 16(-17.78,-1.27) 17(-20.32,1.27)
  rect 1.778x1.778 hole 0.711: A1(20.32,3.81) A2(17.78,1.27) A3(15.24,3.81) A4(12.7,1.27) A5(10.16,3.81) A6(7.62,1.27) A7(5.08,3.81) A8(2.54,1.27) A9(0,3.81) A10(-2.54,1.27) A11(-5.08,3.81) A12(-7.62,1.27) A13(-10.16,3.81) A14(-12.7,1.27) A15(-15.24,3.81) A16(-17.78,1.27) A17(-20.32,3.81) B1(20.32,-1.27) B2(17.78,-3.81) B3(15.24,-1.27) B4(12.7,-3.81) B5(10.16,-1.27) B6(7.62,-3.81) B7(5.08,-1.27) B8(2.54,-3.81) B9(0,-1.27) B10(-2.54,-3.81) B11(-5.08,-1.27) B12(-7.62,-3.81) B13(-10.16,-1.27) B14(-12.7,-3.81) B15(-15.24,-1.27) B16(-17.78,-3.81) B17(-20.32,-1.27)
PG_VG93K_F_G8D431
  round 1.778 hole 0.711: 01(20.32,1.27) 02(17.78,-1.27) 03(15.24,1.27) 04(12.7,-1.27) 05(10.16,1.27) 06(7.62,-1.27) 07(5.08,1.27) 08(2.54,-1.27) 09(0,1.27) 10(-2.54,-1.27) 11(-5.08,1.27) 12(-7.62,-1.27) 13(-10.16,1.27) 14(-12.7,-1.27) 15(-15.24,1.27) 16(-17.78,-1.27) 17(-20.32,1.27)
  rect 1.778x1.778 hole 0.711: A1(20.32,3.81) A2(17.78,1.27) A3(15.24,3.81) A4(12.7,1.27) A5(10.16,3.81) A6(7.62,1.27) A7(5.08,3.81) A8(2.54,1.27) A9(0,3.81) A10(-2.54,1.27) A11(-5.08,3.81) A12(-7.62,1.27) A13(-10.16,3.81) A14(-12.7,1.27) A15(-15.24,3.81) A16(-17.78,1.27) A17(-20.32,3.81) B1(20.32,-1.27) B2(17.78,-3.81) B3(15.24,-1.27) B4(12.7,-3.81) B5(10.16,-1.27) B6(7.62,-3.81) B7(5.08,-1.27) B8(2.54,-3.81) B9(0,-1.27) B10(-2.54,-3.81) B11(-5.08,-1.27) B12(-7.62,-3.81) B13(-10.16,-1.27) B14(-12.7,-3.81) B15(-15.24,-1.27) B16(-17.78,-3.81) B17(-20.32,-1.27)
PG_VG93K_F_G8D432
  round 1.778 hole 0.711: 01(20.32,1.27) 02(17.78,-1.27) 03(15.24,1.27) 04(12.7,-1.27) 05(10.16,1.27) 06(7.62,-1.27) 07(5.08,1.27) 08(2.54,-1.27) 09(0,1.27) 10(-2.54,-1.27) 11(-5.08,1.27) 12(-7.62,-1.27) 13(-10.16,1.27) 14(-12.7,-1.27) 15(-15.24,1.27) 16(-17.78,-1.27) 17(-20.32,1.27)
  rect 1.778x1.778 hole 0.711: A1(20.32,3.81) A2(17.78,1.27) A3(15.24,3.81) A4(12.7,1.27) A5(10.16,3.81) A6(7.62,1.27) A7(5.08,3.81) A8(2.54,1.27) A9(0,3.81) A10(-2.54,1.27) A11(-5.08,3.81) A12(-7.62,1.27) A13(-10.16,3.81) A14(-12.7,1.27) A15(-15.24,3.81) A16(-17.78,1.27) A17(-20.32,3.81) B1(20.32,-1.27) B2(17.78,-3.81) B3(15.24,-1.27) B4(12.7,-3.81) B5(10.16,-1.27) B6(7.62,-3.81) B7(5.08,-1.27) B8(2.54,-3.81) B9(0,-1.27) B10(-2.54,-3.81) B11(-5.08,-1.27) B12(-7.62,-3.81) B13(-10.16,-1.27) B14(-12.7,-3.81) B15(-15.24,-1.27) B16(-17.78,-3.81) B17(-20.32,-1.27)
PG_VG93K_F_G8DPS8
  round 1.778 hole 0.711: A01(20.32,2.54) A02(17.78,2.54) A03(15.24,2.54) A04(12.7,2.54) A05(10.16,2.54) A06(7.62,2.54) A07(5.08,2.54) A08(2.54,2.54) A09(0,2.54) A10(-2.54,2.54) A11(-5.08,2.54) A12(-7.62,2.54) A13(-10.16,2.54) A14(-12.7,2.54) A15(-15.24,2.54) A16(-17.78,2.54) A17(-20.32,2.54) B01(20.32,0) B02(17.78,0) B03(15.24,0) B04(12.7,0) B05(10.16,0) B06(7.62,0) B07(5.08,0) B08(2.54,0) B09(0,0) B10(-2.54,0) B11(-5.08,0) B12(-7.62,0) B13(-10.16,0) B14(-12.7,0) B15(-15.24,0) B16(-17.78,0) B17(-20.32,0) C01(20.32,-2.54) C02(17.78,-2.54) C03(15.24,-2.54) C04(12.7,-2.54) C05(10.16,-2.54) C06(7.62,-2.54) C07(5.08,-2.54) C08(2.54,-2.54) C09(0,-2.54) C10(-2.54,-2.54) C11(-5.08,-2.54) C12(-7.62,-2.54) C13(-10.16,-2.54) C14(-12.7,-2.54) C15(-15.24,-2.54) C16(-17.78,-2.54) C17(-20.32,-2.54)
PG_VG93K_F_G8UTI4
  round 1.778 hole 0.711: A01(20.32,1.27) A02(17.78,1.27) A03(15.24,1.27) A04(12.7,1.27) A05(10.16,1.27) A06(7.62,1.27) A07(5.08,1.27) A08(2.54,1.27) A09(0,1.27) A10(-2.54,1.27) A11(-5.08,1.27) A12(-7.62,1.27) A13(-10.16,1.27) A14(-12.7,1.27) A15(-15.24,1.27) A16(-17.78,1.27) A17(-20.32,1.27) B01(20.32,-1.27) B02(17.78,-1.27) B03(15.24,-1.27) B04(12.7,-1.27) B05(10.16,-1.27) B06(7.62,-1.27) B07(5.08,-1.27) B08(2.54,-1.27) B09(0,-1.27) B10(-2.54,-1.27) B11(-5.08,-1.27) B12(-7.62,-1.27) B13(-10.16,-1.27) B14(-12.7,-1.27) B15(-15.24,-1.27) B16(-17.78,-1.27) B17(-20.32,-1.27)
PG_VG93K_F_HALFOUTLINE_FY
  round 0.508 hole 3.2 unplated: (-140.276,198.12) (-140.276,102.006) (-140.276,0) (-140.276,-102.006) (-140.276,-198.12) (-73.66,157.48) (-73.66,-157.48) (7.044,198.12) (7.044,102.006) (7.044,-102.006) (7.044,-198.12) (73.66,157.48) (73.66,-157.48) (140.304,198.12) (140.304,102.006) (140.304,0) (140.304,-102.006) (140.304,-198.12)
  round 6.096 hole 4.293: NUT19(70,70) NUT20(-70,70) NUT21(-70,-70) NUT22(70,-70)
PG_VG93K_F_PS1600SD_G1_ND
  round 1.778 smd: 01(-20.32,-1.27) 02(-17.78,1.27) 03(-15.24,-1.27) 04(-12.7,1.27) 05(-10.16,-1.27) 06(-7.62,1.27) 07(-5.08,-1.27) 08(-2.54,1.27) 09(0,-1.27) 10(2.54,1.27) 11(5.08,-1.27) 12(7.62,1.27) 13(10.16,-1.27) 14(12.7,1.27) 15(15.24,-1.27) 16(17.78,1.27) 17(20.32,-1.27)
  rect 1.778x1.778 smd: A1(-20.32,-3.81) A2(-17.78,-1.27) A3(-15.24,-3.81) A4(-12.7,-1.27) A5(-10.16,-3.81) A6(-7.62,-1.27) A7(-5.08,-3.81) A8(-2.54,-1.27) A9(0,-3.81) A10(2.54,-1.27) A11(5.08,-3.81) A12(7.62,-1.27) A13(10.16,-3.81) A14(12.7,-1.27) A15(15.24,-3.81) A16(17.78,-1.27) A17(20.32,-3.81) B1(-20.32,1.27) B2(-17.78,3.81) B3(-15.24,1.27) B4(-12.7,3.81) B5(-10.16,1.27) B6(-7.62,3.81) B7(-5.08,1.27) B8(-2.54,3.81) B9(0,1.27) B10(2.54,3.81) B11(5.08,1.27) B12(7.62,3.81) B13(10.16,1.27) B14(12.7,3.81) B15(15.24,1.27) B16(17.78,3.81) B17(20.32,1.27)
PG_VG93K_F_PS1600SD_G2_ND
  round 1.778 smd: 01(20.32,1.27) 02(17.78,-1.27) 03(15.24,1.27) 04(12.7,-1.27) 05(10.16,1.27) 06(7.62,-1.27) 07(5.08,1.27) 08(2.54,-1.27) 09(0,1.27) 10(-2.54,-1.27) 11(-5.08,1.27) 12(-7.62,-1.27) 13(-10.16,1.27) 14(-12.7,-1.27) 15(-15.24,1.27) 16(-17.78,-1.27) 17(-20.32,1.27)
  rect 1.778x1.778 smd: A1(20.32,3.81) A2(17.78,1.27) A3(15.24,3.81) A4(12.7,1.27) A5(10.16,3.81) A6(7.62,1.27) A7(5.08,3.81) A8(2.54,1.27) A9(0,3.81) A10(-2.54,1.27) A11(-5.08,3.81) A12(-7.62,1.27) A13(-10.16,3.81) A14(-12.7,1.27) A15(-15.24,3.81) A16(-17.78,1.27) A17(-20.32,3.81) B1(20.32,-1.27) B2(17.78,-3.81) B3(15.24,-1.27) B4(12.7,-3.81) B5(10.16,-1.27) B6(7.62,-3.81) B7(5.08,-1.27) B8(2.54,-3.81) B9(0,-1.27) B10(-2.54,-3.81) B11(-5.08,-1.27) B12(-7.62,-3.81) B13(-10.16,-1.27) B14(-12.7,-3.81) B15(-15.24,-1.27) B16(-17.78,-3.81) B17(-20.32,-1.27)
PG_VG93K_F_PS1600SD_G3_ND
  round 1.778 smd: 01(-20.32,-1.27) 02(-17.78,1.27) 03(-15.24,-1.27) 04(-12.7,1.27) 05(-10.16,-1.27) 06(-7.62,1.27) 07(-5.08,-1.27) 08(-2.54,1.27) 09(0,-1.27) 10(2.54,1.27) 11(5.08,-1.27) 12(7.62,1.27) 13(10.16,-1.27) 14(12.7,1.27) 15(15.24,-1.27) 16(17.78,1.27) 17(20.32,-1.27)
  rect 1.778x1.778 smd: A1(-20.32,-3.81) A2(-17.78,-1.27) A3(-15.24,-3.81) A4(-12.7,-1.27) A5(-10.16,-3.81) A6(-7.62,-1.27) A7(-5.08,-3.81) A8(-2.54,-1.27) A9(0,-3.81) A10(2.54,-1.27) A11(5.08,-3.81) A12(7.62,-1.27) A13(10.16,-3.81) A14(12.7,-1.27) A15(15.24,-3.81) A16(17.78,-1.27) A17(20.32,-3.81) B1(-20.32,1.27) B2(-17.78,3.81) B3(-15.24,1.27) B4(-12.7,3.81) B5(-10.16,1.27) B6(-7.62,3.81) B7(-5.08,1.27) B8(-2.54,3.81) B9(0,1.27) B10(2.54,3.81) B11(5.08,1.27) B12(7.62,3.81) B13(10.16,1.27) B14(12.7,3.81) B15(15.24,1.27) B16(17.78,3.81) B17(20.32,1.27)
PG_VG93K_PF_DPS32_G8D225
  rect 1.778x1.778 hole 0.711: A1(20.32,3.81) A3(15.24,3.81) A5(10.16,3.81) A7(5.08,3.81) A9(0,3.81) A11(-5.08,3.81) A13(-10.16,3.81) A15(-15.24,3.81) B2(17.78,1.27) B4(12.7,1.27) B6(7.62,1.27) B8(2.54,1.27) B10(-2.54,1.27) B12(-7.62,1.27) B14(-12.7,1.27) B16(-17.78,1.27) C1(20.32,-1.27) C3(15.24,-1.27) C5(10.16,-1.27) C7(5.08,-1.27) C9(0,-1.27) C11(-5.08,-1.27) C13(-10.16,-1.27) C15(-15.24,-1.27) D2(17.78,-3.81) D4(12.7,-3.81) D6(7.62,-3.81) D8(2.54,-3.81) D10(-2.54,-3.81) D12(-7.62,-3.81) D14(-12.7,-3.81) D16(-17.78,-3.81)
  round 1.524 hole 0.711: A2(17.78,3.81) A4(12.7,3.81) A6(7.62,3.81) A8(2.54,3.81) A10(-2.54,3.81) A12(-7.62,3.81) A14(-12.7,3.81) A16(-17.78,3.81) A17(-20.32,3.81) B1(20.32,1.27) B3(15.24,1.27) B5(10.16,1.27) B7(5.08,1.27) B9(0,1.27) B11(-5.08,1.27) B13(-10.16,1.27) B15(-15.24,1.27) B17(-20.32,1.27) C2(17.78,-1.27) C4(12.7,-1.27) C6(7.62,-1.27) C8(2.54,-1.27) C10(-2.54,-1.27) C12(-7.62,-1.27) C14(-12.7,-1.27) C16(-17.78,-1.27) C17(-20.32,-1.27) D1(20.32,-3.81) D3(15.24,-3.81) D5(10.16,-3.81) D7(5.08,-3.81) D9(0,-3.81) D11(-5.08,-3.81) D13(-10.16,-3.81) D15(-15.24,-3.81) D17(-20.32,-3.81)
PG_VG93K_PF_DPS32_G8D226
  rect 1.778x1.778 hole 0.711: A1(20.32,3.81) A3(15.24,3.81) A5(10.16,3.81) A7(5.08,3.81) A9(0,3.81) A11(-5.08,3.81) A13(-10.16,3.81) A15(-15.24,3.81) B2(17.78,1.27) B4(12.7,1.27) B6(7.62,1.27) B8(2.54,1.27) B10(-2.54,1.27) B12(-7.62,1.27) B14(-12.7,1.27) B16(-17.78,1.27) C1(20.32,-1.27) C3(15.24,-1.27) C5(10.16,-1.27) C7(5.08,-1.27) C9(0,-1.27) C11(-5.08,-1.27) C13(-10.16,-1.27) C15(-15.24,-1.27) D2(17.78,-3.81) D4(12.7,-3.81) D6(7.62,-3.81) D8(2.54,-3.81) D10(-2.54,-3.81) D12(-7.62,-3.81) D14(-12.7,-3.81) D16(-17.78,-3.81)
  round 1.524 hole 0.711: A2(17.78,3.81) A4(12.7,3.81) A6(7.62,3.81) A8(2.54,3.81) A10(-2.54,3.81) A12(-7.62,3.81) A14(-12.7,3.81) A16(-17.78,3.81) A17(-20.32,3.81) B1(20.32,1.27) B3(15.24,1.27) B5(10.16,1.27) B7(5.08,1.27) B9(0,1.27) B11(-5.08,1.27) B13(-10.16,1.27) B15(-15.24,1.27) B17(-20.32,1.27) C2(17.78,-1.27) C4(12.7,-1.27) C6(7.62,-1.27) C8(2.54,-1.27) C10(-2.54,-1.27) C12(-7.62,-1.27) C14(-12.7,-1.27) C16(-17.78,-1.27) C17(-20.32,-1.27) D1(20.32,-3.81) D3(15.24,-3.81) D5(10.16,-3.81) D7(5.08,-3.81) D9(0,-3.81) D11(-5.08,-3.81) D13(-10.16,-3.81) D15(-15.24,-3.81) D17(-20.32,-3.81)
PG_VG93K_PF_DPS32_G8D229
  rect 1.778x1.778 hole 0.711: A1(20.32,3.81) A3(15.24,3.81) A5(10.16,3.81) A7(5.08,3.81) A9(0,3.81) A11(-5.08,3.81) A13(-10.16,3.81) A15(-15.24,3.81) B2(17.78,1.27) B4(12.7,1.27) B6(7.62,1.27) B8(2.54,1.27) B10(-2.54,1.27) B12(-7.62,1.27) B14(-12.7,1.27) B16(-17.78,1.27) C1(20.32,-1.27) C3(15.24,-1.27) C5(10.16,-1.27) C7(5.08,-1.27) C9(0,-1.27) C11(-5.08,-1.27) C13(-10.16,-1.27) C15(-15.24,-1.27) D2(17.78,-3.81) D4(12.7,-3.81) D6(7.62,-3.81) D8(2.54,-3.81) D10(-2.54,-3.81) D12(-7.62,-3.81) D14(-12.7,-3.81) D16(-17.78,-3.81)
  round 1.524 hole 0.711: A2(17.78,3.81) A4(12.7,3.81) A6(7.62,3.81) A8(2.54,3.81) A10(-2.54,3.81) A12(-7.62,3.81) A14(-12.7,3.81) A16(-17.78,3.81) A17(-20.32,3.81) B1(20.32,1.27) B3(15.24,1.27) B5(10.16,1.27) B7(5.08,1.27) B9(0,1.27) B11(-5.08,1.27) B13(-10.16,1.27) B15(-15.24,1.27) B17(-20.32,1.27) C2(17.78,-1.27) C4(12.7,-1.27) C6(7.62,-1.27) C8(2.54,-1.27) C10(-2.54,-1.27) C12(-7.62,-1.27) C14(-12.7,-1.27) C16(-17.78,-1.27) C17(-20.32,-1.27) D1(20.32,-3.81) D3(15.24,-3.81) D5(10.16,-3.81) D7(5.08,-3.81) D9(0,-3.81) D11(-5.08,-3.81) D13(-10.16,-3.81) D15(-15.24,-3.81) D17(-20.32,-3.81)
PG_VG93K_PF_DPS32_G8D425
  rect 1.778x1.778 hole 0.711: A1(20.32,3.81) A3(15.24,3.81) A5(10.16,3.81) A7(5.08,3.81) A9(0,3.81) A11(-5.08,3.81) A13(-10.16,3.81) A15(-15.24,3.81) B2(17.78,1.27) B4(12.7,1.27) B6(7.62,1.27) B8(2.54,1.27) B10(-2.54,1.27) B12(-7.62,1.27) B14(-12.7,1.27) B16(-17.78,1.27) C1(20.32,-1.27) C3(15.24,-1.27) C5(10.16,-1.27) C7(5.08,-1.27) C9(0,-1.27) C11(-5.08,-1.27) C13(-10.16,-1.27) C15(-15.24,-1.27) D2(17.78,-3.81) D4(12.7,-3.81) D6(7.62,-3.81) D8(2.54,-3.81) D10(-2.54,-3.81) D12(-7.62,-3.81) D14(-12.7,-3.81) D16(-17.78,-3.81)
  round 1.524 hole 0.711: A2(17.78,3.81) A4(12.7,3.81) A6(7.62,3.81) A8(2.54,3.81) A10(-2.54,3.81) A12(-7.62,3.81) A14(-12.7,3.81) A16(-17.78,3.81) A17(-20.32,3.81) B1(20.32,1.27) B3(15.24,1.27) B5(10.16,1.27) B7(5.08,1.27) B9(0,1.27) B11(-5.08,1.27) B13(-10.16,1.27) B15(-15.24,1.27) B17(-20.32,1.27) C2(17.78,-1.27) C4(12.7,-1.27) C6(7.62,-1.27) C8(2.54,-1.27) C10(-2.54,-1.27) C12(-7.62,-1.27) C14(-12.7,-1.27) C16(-17.78,-1.27) C17(-20.32,-1.27) D1(20.32,-3.81) D3(15.24,-3.81) D5(10.16,-3.81) D7(5.08,-3.81) D9(0,-3.81) D11(-5.08,-3.81) D13(-10.16,-3.81) D15(-15.24,-3.81) D17(-20.32,-3.81)
PG_VG93K_PF_DPS32_G8D426
  rect 1.778x1.778 hole 0.711: A1(20.32,3.81) A3(15.24,3.81) A5(10.16,3.81) A7(5.08,3.81) A9(0,3.81) A11(-5.08,3.81) A13(-10.16,3.81) A15(-15.24,3.81) B2(17.78,1.27) B4(12.7,1.27) B6(7.62,1.27) B8(2.54,1.27) B10(-2.54,1.27) B12(-7.62,1.27) B14(-12.7,1.27) B16(-17.78,1.27) C1(20.32,-1.27) C3(15.24,-1.27) C5(10.16,-1.27) C7(5.08,-1.27) C9(0,-1.27) C11(-5.08,-1.27) C13(-10.16,-1.27) C15(-15.24,-1.27) D2(17.78,-3.81) D4(12.7,-3.81) D6(7.62,-3.81) D8(2.54,-3.81) D10(-2.54,-3.81) D12(-7.62,-3.81) D14(-12.7,-3.81) D16(-17.78,-3.81)
  round 1.524 hole 0.711: A2(17.78,3.81) A4(12.7,3.81) A6(7.62,3.81) A8(2.54,3.81) A10(-2.54,3.81) A12(-7.62,3.81) A14(-12.7,3.81) A16(-17.78,3.81) A17(-20.32,3.81) B1(20.32,1.27) B3(15.24,1.27) B5(10.16,1.27) B7(5.08,1.27) B9(0,1.27) B11(-5.08,1.27) B13(-10.16,1.27) B15(-15.24,1.27) B17(-20.32,1.27) C2(17.78,-1.27) C4(12.7,-1.27) C6(7.62,-1.27) C8(2.54,-1.27) C10(-2.54,-1.27) C12(-7.62,-1.27) C14(-12.7,-1.27) C16(-17.78,-1.27) C17(-20.32,-1.27) D1(20.32,-3.81) D3(15.24,-3.81) D5(10.16,-3.81) D7(5.08,-3.81) D9(0,-3.81) D11(-5.08,-3.81) D13(-10.16,-3.81) D15(-15.24,-3.81) D17(-20.32,-3.81)
PG_VG93K_PF_DPS32_G8D429
  rect 1.778x1.778 hole 0.711: A1(20.32,3.81) A3(15.24,3.81) A5(10.16,3.81) A7(5.08,3.81) A9(0,3.81) A11(-5.08,3.81) A13(-10.16,3.81) A15(-15.24,3.81) B2(17.78,1.27) B4(12.7,1.27) B6(7.62,1.27) B8(2.54,1.27) B10(-2.54,1.27) B12(-7.62,1.27) B14(-12.7,1.27) B16(-17.78,1.27) C1(20.32,-1.27) C3(15.24,-1.27) C5(10.16,-1.27) C7(5.08,-1.27) C9(0,-1.27) C11(-5.08,-1.27) C13(-10.16,-1.27) C15(-15.24,-1.27) D2(17.78,-3.81) D4(12.7,-3.81) D6(7.62,-3.81) D8(2.54,-3.81) D10(-2.54,-3.81) D12(-7.62,-3.81) D14(-12.7,-3.81) D16(-17.78,-3.81)
  round 1.524 hole 0.711: A2(17.78,3.81) A4(12.7,3.81) A6(7.62,3.81) A8(2.54,3.81) A10(-2.54,3.81) A12(-7.62,3.81) A14(-12.7,3.81) A16(-17.78,3.81) A17(-20.32,3.81) B1(20.32,1.27) B3(15.24,1.27) B5(10.16,1.27) B7(5.08,1.27) B9(0,1.27) B11(-5.08,1.27) B13(-10.16,1.27) B15(-15.24,1.27) B17(-20.32,1.27) C2(17.78,-1.27) C4(12.7,-1.27) C6(7.62,-1.27) C8(2.54,-1.27) C10(-2.54,-1.27) C12(-7.62,-1.27) C14(-12.7,-1.27) C16(-17.78,-1.27) C17(-20.32,-1.27) D1(20.32,-3.81) D3(15.24,-3.81) D5(10.16,-3.81) D7(5.08,-3.81) D9(0,-3.81) D11(-5.08,-3.81) D13(-10.16,-3.81) D15(-15.24,-3.81) D17(-20.32,-3.81)
PG_VG93K_PF_UHC4_G8D230_A34_V2
  round 1.524 hole 0.711: A1(20.325,2.625) A2(18.575,2.625) A3(16.825,2.625) A4(15.075,2.625) B1(20.325,0.875) B2(18.575,0.875) B3(16.825,0.875) B4(15.075,0.875) C1(20.325,-0.875) C2(18.575,-0.875) C3(16.825,-0.875) C4(15.075,-0.875) D1(20.325,-2.625) D2(18.575,-2.625) D3(16.825,-2.625) D4(15.075,-2.625)
  rect 5.6x8.3 smd: G3(10.85,0) G4(-18.95,0)
  round 1.27 hole 0.711: G3_1(13.15,3.5) G3_2(10.85,3.5) G3_3(8.55,3.5) G3_4(12,1.75) G3_5(9.7,1.75) G3_6(13.15,0) G3_7(10.85,0) G3_8(8.55,0) G3_9(12,-1.75) G3_10(9.7,-1.75) G3_11(13.15,-3.5) G3_12(10.85,-3.5) G3_13(8.55,-3.5) G4_1(-16.65,3.5) G4_2(-18.95,3.5) G4_3(-21.25,3.5) G4_4(-17.8,1.75) G4_5(-20.1,1.75) G4_6(-16.65,0) G4_7(-18.95,0) G4_8(-21.25,0) G4_9(-17.8,-1.75) G4_10(-20.1,-1.75) G4_11(-16.65,-3.5) G4_12(-18.95,-3.5) G4_13(-21.25,-3.5) P3_1(6.55,3.5) P3_2(3.35,3.5) P3_3(0.15,3.5) P3_4(-3.05,3.5) P3_5(6.55,0) P3_6(3.35,0) P3_7(0.15,0) P3_8(-3.05,0) P3_9(6.55,-3.5) P3_10(3.35,-3.5) P3_11(0.15,-3.5) P3_12(-3.05,-3.5) P3_13(4.95,1.75) P3_14(1.75,1.75) P3_15(-1.45,1.75) P3_16(4.95,-1.75) P3_17(1.75,-1.75) P3_18(-1.45,-1.75) P4_1(-5.05,3.5) P4_2(-8.25,3.5) P4_3(-11.45,3.5) P4_4(-14.65,3.5) P4_5(-5.05,0) P4_6(-8.25,0) P4_7(-11.45,0) P4_8(-14.65,0) P4_9(-5.05,-3.5) P4_10(-8.25,-3.5) P4_11(-11.45,-3.5) P4_12(-14.65,-3.5) P4_13(-6.65,1.75) P4_14(-9.85,1.75) P4_15(-13.05,1.75) P4_16(-6.65,-1.75) P4_17(-9.85,-1.75) P4_18(-13.05,-1.75)
  rect 10.6x8.3 smd: P3(1.75,0) P4(-9.85,0)
PG_VG93K_PF_UHC4_G8D430_B12_V2
  round 1.524 hole 0.711: A1(20.325,2.625) A2(18.575,2.625) A3(16.825,2.625) A4(15.075,2.625) B1(20.325,0.875) B2(18.575,0.875) B3(16.825,0.875) B4(15.075,0.875) C1(20.325,-0.875) C2(18.575,-0.875) C3(16.825,-0.875) C4(15.075,-0.875) D1(20.325,-2.625) D2(18.575,-2.625) D3(16.825,-2.625) D4(15.075,-2.625)
  rect 5.6x8.3 smd: G1(-18.95,0) G2(10.85,0)
  round 1.27 hole 0.711: G1_1(-16.65,3.5) G1_2(-18.95,3.5) G1_3(-21.25,3.5) G1_4(-17.8,1.75) G1_5(-20.1,1.75) G1_6(-16.65,0) G1_7(-18.95,0) G1_8(-21.25,0) G1_9(-17.8,-1.75) G1_10(-20.1,-1.75) G1_11(-16.65,-3.5) G1_12(-18.95,-3.5) G1_13(-21.25,-3.5) G2_1(13.15,3.5) G2_2(10.85,3.5) G2_3(8.55,3.5) G2_4(12,1.75) G2_5(9.7,1.75) G2_6(13.15,0) G2_7(10.85,0) G2_8(8.55,0) G2_9(12,-1.75) G2_10(9.7,-1.75) G2_11(13.15,-3.5) G2_12(10.85,-3.5) G2_13(8.55,-3.5) P1_1(-5.05,3.5) P1_2(-8.25,3.5) P1_3(-11.45,3.5) P1_4(-14.65,3.5) P1_5(-5.05,0) P1_6(-8.25,0) P1_7(-11.45,0) P1_8(-14.65,0) P1_9(-5.05,-3.5) P1_10(-8.25,-3.5) P1_11(-11.45,-3.5) P1_12(-14.65,-3.5) P1_13(-6.65,1.75) P1_14(-9.85,1.75) P1_15(-13.05,1.75) P1_16(-6.65,-1.75) P1_17(-9.85,-1.75) P1_18(-13.05,-1.75) P2_1(6.55,3.5) P2_2(3.35,3.5) P2_3(0.15,3.5) P2_4(-3.05,3.5) P2_5(6.55,0) P2_6(3.35,0) P2_7(0.15,0) P2_8(-3.05,0) P2_9(6.55,-3.5) P2_10(3.35,-3.5) P2_11(0.15,-3.5) P2_12(-3.05,-3.5) P2_13(4.95,1.75) P2_14(1.75,1.75) P2_15(-1.45,1.75) P2_16(4.95,-1.75) P2_17(1.75,-1.75) P2_18(-1.45,-1.75)
  rect 10.6x8.3 smd: P1(-9.85,0) P2(1.75,0)
R0402
  custom 0.15x0.15 smd: 1(-0.5,0) 2(0.5,0)
R0402_UNBGA_V2
  rect 0.508x0.508 smd: 1(-0.425,0) 2(0.425,0)
R0603
  rect 0.889x0.889 smd: 1(-0.85,0) 2(0.85,0)
R0805
  rect 1.118x1.372 smd: 1(-0.95,0) 2(0.95,0)
R1206
  rect 1.321x1.829 smd: 1(-1.25,0) 2(1.25,0)
RL_712D_5V_V2
  round 1.397 hole 1.041: 1(1.493,-2.055) 2(2.416,-0.785) 3(2.416,0.785) 4(1.493,2.055) 6(-1.493,2.055) 7(-2.416,0.785) 8(-2.416,-0.785) 9(-1.493,-2.055)
RL_COTO2911_5V_RLPIN
  rect 1.88x1.88 hole 1.372: 1(17.78,0)
  round 0.051 smd: 2(15.24,0)
  round 1.88 hole 1.372: 3(2.54,0) 4(0,0) 5(0,-2.54) 6(2.54,-2.54) 7(15.24,-2.54) 8(17.78,-2.54)
RL_NECUA2_5V_V3
  rect 1.626x1.626 hole 1.041: 1(3.6,1.6)
  round 1.626 hole 1.041: 2(0.4,1.6) 3(-1.8,1.6) 4(-4,1.6) 5(-4,-1.6) 6(-1.8,-1.6) 7(0.4,-1.6) 8(3.6,-1.6)
SK_BGA17X17_336P_0P8MM_S071AA
  round 0.508 hole 1.61 unplated: (-12,12) (-12,-12) (12,12) (12,-12)
  round 0.6 smd: A1(-7.6,7.6) A2(-6.8,7.6) A3(-6,7.6) A4(-5.2,7.6) A5(-4.4,7.6) A6(-3.6,7.6) A7(-2.8,7.6) A8(-2,7.6) A9(-1.2,7.6) A10(-0.4,7.6) A11(0.4,7.6) A12(1.2,7.6) A13(2,7.6) A14(2.8,7.6) A15(3.6,7.6) A16(4.4,7.6) A17(5.2,7.6) A18(6,7.6) A19(6.8,7.6) A20(7.6,7.6) B1(-7.6,6.8) B2(-6.8,6.8) B3(-6,6.8) B4(-5.2,6.8) B5(-4.4,6.8) B6(-3.6,6.8) B7(-2.8,6.8) B8(-2,6.8) B9(-1.2,6.8) B10(-0.4,6.8) B11(0.4,6.8) B12(1.2,6.8) B13(2,6.8) B14(2.8,6.8) B15(3.6,6.8) B16(4.4,6.8) B17(5.2,6.8) B18(6,6.8) B19(6.8,6.8) B20(7.6,6.8) C1(-7.6,6) C2(-6.8,6) C3(-6,6) C4(-5.2,6) C5(-4.4,6) C6(-3.6,6) C7(-2.8,6) C8(-2,6) C9(-1.2,6) C10(-0.4,6) C11(0.4,6) C12(1.2,6) C13(2,6) C14(2.8,6) C15(3.6,6) C16(4.4,6) C17(5.2,6) C18(6,6) C19(6.8,6) C20(7.6,6) D1(-7.6,5.2) D2(-6.8,5.2) D3(-6,5.2) D4(-5.2,5.2) D5(-4.4,5.2) D6(-3.6,5.2) D7(-2.8,5.2) D8(-2,5.2) D9(-1.2,5.2) D10(-0.4,5.2) D11(0.4,5.2) D12(1.2,5.2) D13(2,5.2) D14(2.8,5.2) D15(3.6,5.2) D16(4.4,5.2) D17(5.2,5.2) D18(6,5.2) D19(6.8,5.2) D20(7.6,5.2) E1(-7.6,4.4) E2(-6.8,4.4) E3(-6,4.4) E4(-5.2,4.4) E5(-4.4,4.4) E6(-3.6,4.4) E7(-2.8,4.4) E8(-2,4.4) E9(-1.2,4.4) E10(-0.4,4.4) E11(0.4,4.4) E12(1.2,4.4) E13(2,4.4) E14(2.8,4.4) E15(3.6,4.4) E16(4.4,4.4) E17(5.2,4.4) E18(6,4.4) E19(6.8,4.4) E20(7.6,4.4) F1(-7.6,3.6) F2(-6.8,3.6) F3(-6,3.6) F4(-5.2,3.6) F5(-4.4,3.6) F16(4.4,3.6) F17(5.2,3.6) F18(6,3.6) F19(6.8,3.6) F20(7.6,3.6) G1(-7.6,2.8) G2(-6.8,2.8) G3(-6,2.8) G4(-5.2,2.8) G5(-4.4,2.8) G16(4.4,2.8) G17(5.2,2.8) G18(6,2.8) G19(6.8,2.8) G20(7.6,2.8) H1(-7.6,2) H2(-6.8,2) H3(-6,2) H4(-5.2,2) H5(-4.4,2) H8(-2,2) H9(-1.2,2) H10(-0.4,2) H11(0.4,2) H12(1.2,2) H13(2,2) H16(4.4,2) H17(5.2,2) H18(6,2) H19(6.8,2) H20(7.6,2) J1(-7.6,1.2) J2(-6.8,1.2) J3(-6,1.2) J4(-5.2,1.2) J5(-4.4,1.2) J8(-2,1.2) J9(-1.2,1.2) J10(-0.4,1.2) J11(0.4,1.2) J12(1.2,1.2) J13(2,1.2) J16(4.4,1.2) J17(5.2,1.2) J18(6,1.2) J19(6.8,1.2) J20(7.6,1.2) K1(-7.6,0.4) K2(-6.8,0.4) K3(-6,0.4) K4(-5.2,0.4) K5(-4.4,0.4) K8(-2,0.4) K9(-1.2,0.4) K10(-0.4,0.4) K11(0.4,0.4) K12(1.2,0.4) K13(2,0.4) K16(4.4,0.4) K17(5.2,0.4) K18(6,0.4) K19(6.8,0.4) K20(7.6,0.4) L1(-7.6,-0.4) L2(-6.8,-0.4) L3(-6,-0.4) L4(-5.2,-0.4) L5(-4.4,-0.4) L8(-2,-0.4) L9(-1.2,-0.4) L10(-0.4,-0.4) L11(0.4,-0.4) L12(1.2,-0.4) L13(2,-0.4) L16(4.4,-0.4) L17(5.2,-0.4) L18(6,-0.4) L19(6.8,-0.4) L20(7.6,-0.4) M1(-7.6,-1.2) M2(-6.8,-1.2) M3(-6,-1.2) M4(-5.2,-1.2) M5(-4.4,-1.2) M8(-2,-1.2) M9(-1.2,-1.2) M10(-0.4,-1.2) M11(0.4,-1.2) M12(1.2,-1.2) M13(2,-1.2) M16(4.4,-1.2) M17(5.2,-1.2) M18(6,-1.2) M19(6.8,-1.2) M20(7.6,-1.2) N1(-7.6,-2) N2(-6.8,-2) N3(-6,-2) N4(-5.2,-2) N5(-4.4,-2) N8(-2,-2) N9(-1.2,-2) N10(-0.4,-2) N11(0.4,-2) N12(1.2,-2) N13(2,-2) N16(4.4,-2) N17(5.2,-2) N18(6,-2) N19(6.8,-2) N20(7.6,-2) P1(-7.6,-2.8) P2(-6.8,-2.8) P3(-6,-2.8) P4(-5.2,-2.8) P5(-4.4,-2.8) P16(4.4,-2.8) P17(5.2,-2.8) P18(6,-2.8) P19(6.8,-2.8) P20(7.6,-2.8) R1(-7.6,-3.6) R2(-6.8,-3.6) R3(-6,-3.6) R4(-5.2,-3.6) R5(-4.4,-3.6) R16(4.4,-3.6) R17(5.2,-3.6) R18(6,-3.6) R19(6.8,-3.6) R20(7.6,-3.6) T1(-7.6,-4.4) T2(-6.8,-4.4) T3(-6,-4.4) T4(-5.2,-4.4) T5(-4.4,-4.4) T6(-3.6,-4.4) T7(-2.8,-4.4) T8(-2,-4.4) T9(-1.2,-4.4) T10(-0.4,-4.4) T11(0.4,-4.4) T12(1.2,-4.4) T13(2,-4.4) T14(2.8,-4.4) T15(3.6,-4.4) T16(4.4,-4.4) T17(5.2,-4.4) T18(6,-4.4) T19(6.8,-4.4) T20(7.6,-4.4) U1(-7.6,-5.2) U2(-6.8,-5.2) U3(-6,-5.2) U4(-5.2,-5.2) U5(-4.4,-5.2) U6(-3.6,-5.2) U7(-2.8,-5.2) U8(-2,-5.2) U9(-1.2,-5.2) U10(-0.4,-5.2) U11(0.4,-5.2) U12(1.2,-5.2) U13(2,-5.2) U14(2.8,-5.2) U15(3.6,-5.2) U16(4.4,-5.2) U17(5.2,-5.2) U18(6,-5.2) U19(6.8,-5.2) U20(7.6,-5.2) V1(-7.6,-6) V2(-6.8,-6) V3(-6,-6) V4(-5.2,-6) V5(-4.4,-6) V6(-3.6,-6) V7(-2.8,-6) V8(-2,-6) V9(-1.2,-6) V10(-0.4,-6) V11(0.4,-6) V12(1.2,-6) V13(2,-6) V14(2.8,-6) V15(3.6,-6) V16(4.4,-6) V17(5.2,-6) V18(6,-6) V19(6.8,-6) V20(7.6,-6) W1(-7.6,-6.8) W2(-6.8,-6.8) W3(-6,-6.8) W4(-5.2,-6.8) W5(-4.4,-6.8) W6(-3.6,-6.8) W7(-2.8,-6.8) W8(-2,-6.8) W9(-1.2,-6.8) W10(-0.4,-6.8) W11(0.4,-6.8) W12(1.2,-6.8) W13(2,-6.8) W14(2.8,-6.8) W15(3.6,-6.8) W16(4.4,-6.8) W17(5.2,-6.8) W18(6,-6.8) W19(6.8,-6.8) W20(7.6,-6.8) Y1(-7.6,-7.6) Y2(-6.8,-7.6) Y3(-6,-7.6) Y4(-5.2,-7.6) Y5(-4.4,-7.6) Y6(-3.6,-7.6) Y7(-2.8,-7.6) Y8(-2,-7.6) Y9(-1.2,-7.6) Y10(-0.4,-7.6) Y11(0.4,-7.6) Y12(1.2,-7.6) Y13(2,-7.6) Y14(2.8,-7.6) Y15(3.6,-7.6) Y16(4.4,-7.6) Y17(5.2,-7.6) Y18(6,-7.6) Y19(6.8,-7.6) Y20(7.6,-7.6)
  round 6.502 hole 4.293: NUT1(-21,21) NUT2(21,21) NUT3(-21,-21) NUT4(21,-21) NUT5(-16,16) NUT6(16,16) NUT7(-16,-16) NUT8(16,-16)
